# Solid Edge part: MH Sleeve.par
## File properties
Author: Dan
Template: FH Insert .par
Last saved by: Dan
Revision: 24
Application: Solid Edge
Density: 7833.000 kg/m^3
Accuracy: 0.990
Material: Steel
Face Style: Steel
Fill Style: ANSI32(Steel)
Virtual Style: Machined steel
Coef. of Thermal Exp: 1.3e-05
Thermal Conductivity: 32.0
Specific Heat: 481.0
Modulus of Elasticity: 199947953000.0
Poisson's Ratio: 0.29
Yield Stress: 262000766.0
Ultimate Stress: 358527364.0
Elongation: 0.0
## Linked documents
FH Insert .par
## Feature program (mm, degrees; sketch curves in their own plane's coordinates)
part copy "CopiedPart_1"
sketch for "ExtrudedProtrusion_1" plane through (0, 0, -36) normal (0, 0, -1) x-axis (-1, 0, 0)
  circle centre (0, 0) radius 22.5
extrude "ExtrudedProtrusion_1" add finite 5 along -normal
sketch for "Hole_1" plane through (0, 0, -36) normal (0, 0, -1) x-axis (-1, 0, 0)
  hole centre (0, 0) bore radius 9
hole "Hole_1" finite  CounterBoreDepth = 1.8 mm
sketch for "unnamed Cutout 1" plane through (0, 0, -15.2481) normal (0, 0, 1) x-axis (1, 0, 0)
extrude "unnamed Cutout 1" cut through
sketch for "ExtrudedCutout_2" plane through (0, 0, -142) normal (0, 0, -1) x-axis (-1, 0, 0)
extrude "ExtrudedCutout_2" cut finite 95 along -normal
sketch for "ExtrudedProtrusion_2" #1 plane through (0, 0, -142) normal (0, 0, -1) x-axis (-1, 0, 0)
sketch for "ExtrudedProtrusion_2" #2 plane through (0, 0, -142) normal (0, 0, -1) x-axis (-1, 0, 0)
extrude "ExtrudedProtrusion_2" add finite 65 along -normal
delete faces "unnamed DeleteFaces 1"
Other named dimensions: "Face_Move_1": Distance = 106 mm
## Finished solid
Body 1: solid body, 14 faces, 14 edges, 0 vertices.
  Faces by surface: plane 7, cylinder 5, cone 2
  Edges by curve: circle 14
Bounding box of the edges (mm): 45.000 x 45.000 x 136.000, from (-22.5, -22.5, -142) to (22.5, 22.5, -6).
Cylindrical faces by radius (mm): R16.75 x1, R16.9 x1, R18.8116 x1, R19.5 x1, R22.5 x1
Conical faces (half-angle, radius in mm at the cone's reference point): 1 deg R18.3793 x1, 2 deg R17.0012 x1
Planar faces by outward normal: +z 5, -z 2
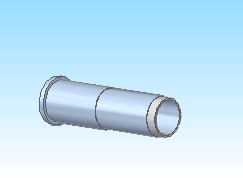
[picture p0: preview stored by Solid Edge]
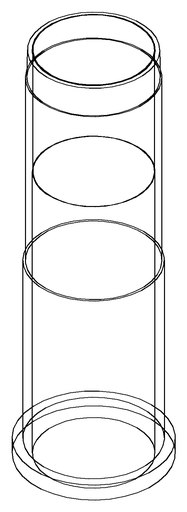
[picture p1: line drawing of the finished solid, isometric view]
